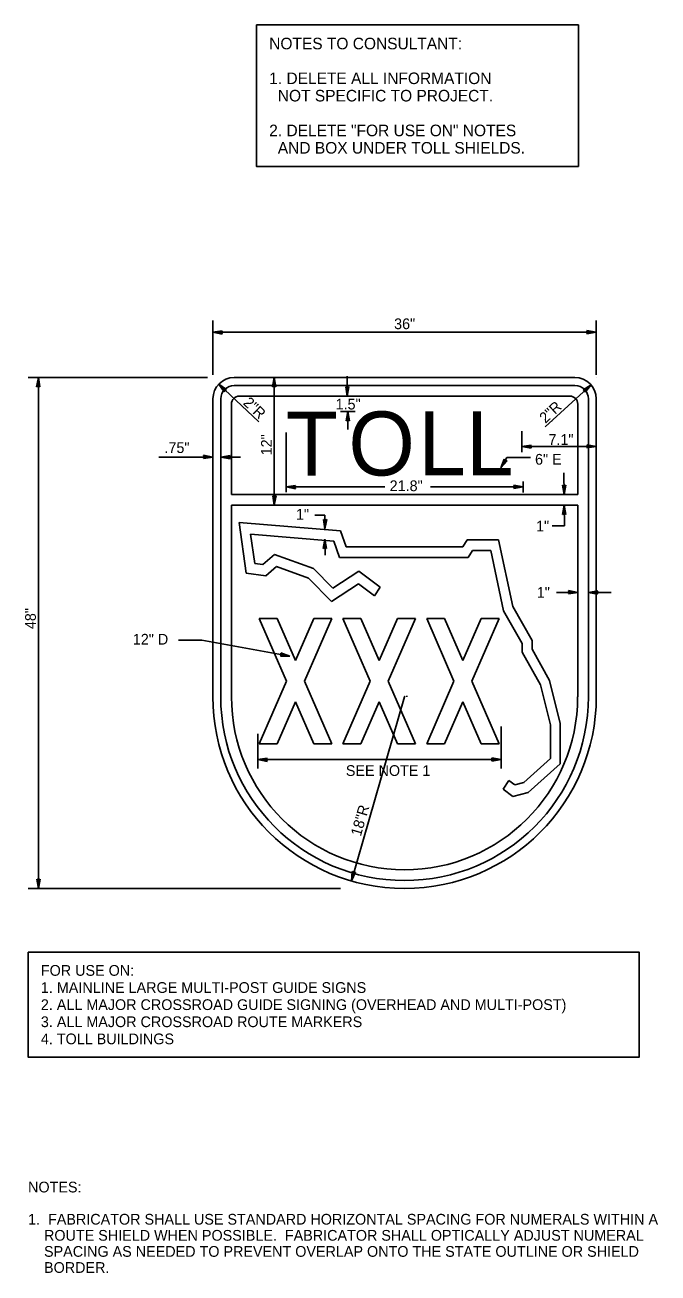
# Model space of a CAD drawing. Extents: x 52194 to 54069, y 8993 to 10153.
# Drawn here: x 52877 to 53372, y 9176 to 10153 of the extents above; entities that cross this region are included whole.
import ezdxf

# ---------------------------------------------------------------- set-up
doc = ezdxf.new("R2010")
doc.units = 0
for name, color, linetype in [('GSDims', 7, 'Continuous'), ('SignPanel', 7, 'Continuous'), ('TextAlert', 7, 'Continuous'), ('TextLabel', 7, 'Continuous'), ('TextNotes', 7, 'Continuous')]:
    doc.layers.add(name, color=color, linetype=linetype)

msp = doc.modelspace()

# ---------------------------------------------------------------- linework, layer by layer
at = {"layer": 'GSDims'}
for p, q in [((53023.82, 9879.03), (53023.82, 9921.63)), ((53323.82, 9879.03), (53323.82, 9921.63)), ((53023.82, 9912.43), (53031.12, 9913.53)), ((53023.82, 9912.43), (53030.82, 9912.93)), ((53023.82, 9912.43), (53031.12, 9911.03)), ((53023.82, 9912.43), (53030.82, 9911.63)), ((53323.82, 9912.43), (53023.82, 9912.43)), ((53030.62, 9912.33), (53031.12, 9913.53)), ((53031.12, 9911.03), (53030.62, 9912.33)), ((53323.82, 9912.43), (53316.52, 9913.83)), ((53316.52, 9913.83), (53317.02, 9912.53)), ((53317.02, 9912.53), (53316.52, 9911.23)), ((53323.82, 9912.43), (53316.52, 9911.23)), ((53323.82, 9912.43), (53316.82, 9913.13)), ((53323.82, 9912.43), (53316.82, 9911.93)), ((53019.42, 9877.03), (52879.12, 9877.03)), ((52887.22, 9877.03), (52885.82, 9869.73)), ((52885.82, 9869.73), (52887.12, 9870.23)), ((52887.22, 9877.03), (52886.42, 9870.03)), ((52887.12, 9870.23), (52888.32, 9869.73)), ((52887.22, 9877.03), (52888.32, 9869.73)), ((52887.22, 9877.03), (52887.72, 9870.03)), ((52887.22, 9877.03), (52887.22, 9477.03)), ((52923.72, 9877.03), (52923.72, 9877.03)), ((53028.42, 9871.88), (53059.72, 9842.43)), ((53028.42, 9871.88), (53034.52, 9867.68)), ((53028.42, 9871.88), (53032.72, 9865.88)), ((53028.42, 9871.88), (53033.02, 9866.58)), ((53028.42, 9871.88), (53033.92, 9867.38)), ((53071.82, 9877.03), (53070.42, 9869.73)), ((53070.42, 9869.73), (53071.72, 9870.33)), ((53071.82, 9877.03), (53071.12, 9870.03)), ((53071.72, 9870.33), (53073.02, 9869.73)), ((53071.82, 9877.03), (53073.02, 9869.73)), ((53071.82, 9877.03), (53072.32, 9870.03)), ((53071.82, 9777.03), (53071.82, 9877.03)), ((53128.87, 9862.43), (53127.72, 9869.73)), ((53128.97, 9869.18), (53127.72, 9869.73)), ((53128.87, 9862.43), (53128.37, 9869.43)), ((53128.87, 9862.43), (53128.87, 9878.08)), ((53128.87, 9862.43), (53130.27, 9869.68)), ((53128.87, 9862.43), (53129.62, 9869.43)), ((53130.27, 9869.68), (53128.97, 9869.18)), ((53319.77, 9871.28), (53283.92, 9838.33)), ((53319.77, 9871.28), (53313.47, 9867.38)), ((53319.77, 9871.28), (53314.07, 9867.08)), ((53319.77, 9871.28), (53314.97, 9866.18)), ((53319.77, 9871.28), (53315.17, 9865.48)), ((53323.82, 9877.03), (53323.82, 9877.03)), ((53032.72, 9865.88), (53033.22, 9867.18)), ((53033.22, 9867.18), (53034.52, 9867.68)), ((53313.47, 9867.38), (53314.67, 9866.78)), ((53314.67, 9866.78), (53315.17, 9865.48)), ((53123.72, 9850.38), (53135.12, 9850.38)), ((53129.42, 9850.38), (53128.02, 9843.13)), ((53129.42, 9850.38), (53128.67, 9843.38)), ((53129.42, 9850.38), (53129.42, 9836.43)), ((53129.42, 9850.38), (53130.57, 9843.08)), ((53129.42, 9850.38), (53129.92, 9843.38)), ((53128.02, 9843.13), (53129.32, 9843.63)), ((53129.32, 9843.63), (53130.57, 9843.08)), ((53289.47, 9842.43), (53289.47, 9842.43)), ((53081.12, 9787.23), (53081.12, 9834.03)), ((53265.62, 9818.48), (53265.62, 9835.03)), ((53265.62, 9823.03), (53272.92, 9824.18)), ((53265.62, 9823.03), (53272.62, 9823.53)), ((53265.62, 9823.03), (53323.82, 9823.03)), ((53265.62, 9823.03), (53272.87, 9821.63)), ((53265.62, 9823.03), (53272.62, 9822.28)), ((53272.37, 9822.93), (53272.92, 9824.18)), ((53272.87, 9821.63), (53272.37, 9822.93)), ((53317.07, 9823.13), (53316.52, 9821.88)), ((53323.82, 9823.03), (53316.52, 9821.88)), ((53323.82, 9823.03), (53316.57, 9824.43)), ((53316.57, 9824.43), (53317.07, 9823.13)), ((53323.82, 9823.03), (53316.82, 9823.78)), ((53323.82, 9823.03), (53316.82, 9822.53)), ((52981.47, 9814.73), (53023.82, 9814.73)), ((53023.82, 9814.73), (53016.52, 9816.13)), ((53016.52, 9816.13), (53017.02, 9814.83)), ((53017.02, 9814.83), (53016.52, 9813.63)), ((53023.82, 9814.73), (53016.52, 9813.63)), ((53023.82, 9814.73), (53016.82, 9815.53)), ((53023.82, 9814.73), (53016.82, 9814.23)), ((53030.02, 9814.73), (53037.32, 9815.93)), ((53030.02, 9814.73), (53037.02, 9815.23)), ((53030.02, 9814.73), (53037.22, 9813.33)), ((53030.02, 9814.73), (53037.02, 9814.03)), ((53030.02, 9814.73), (53045.32, 9814.73)), ((53036.72, 9814.63), (53037.32, 9815.93)), ((53037.22, 9813.33), (53036.72, 9814.63)), ((53249.07, 9806.28), (53253.77, 9814.43)), ((53249.07, 9806.28), (53251.67, 9813.18)), ((53249.07, 9806.28), (53252.17, 9812.58)), ((53249.07, 9806.28), (53253.17, 9811.98)), ((53249.07, 9806.28), (53253.97, 9811.88)), ((53252.57, 9812.08), (53251.67, 9813.18)), ((53253.97, 9811.88), (53252.57, 9812.08)), ((53272.42, 9814.43), (53253.77, 9814.43)), ((53298.62, 9785.38), (53298.42, 9802.28)), ((53081.12, 9791.33), (53088.42, 9792.53)), ((53081.12, 9791.33), (53088.12, 9791.83)), ((53081.12, 9791.33), (53088.42, 9789.93)), ((53081.12, 9791.33), (53088.12, 9790.63)), ((53081.12, 9791.33), (53158.22, 9791.33)), ((53087.82, 9791.23), (53088.42, 9792.53)), ((53088.42, 9789.93), (53087.82, 9791.23)), ((53193.98, 9791.33), (53266.52, 9791.33)), ((53266.52, 9791.33), (53259.22, 9792.73)), ((53259.22, 9792.73), (53259.82, 9791.43)), ((53259.82, 9791.43), (53259.22, 9790.13)), ((53266.52, 9791.33), (53259.22, 9790.13)), ((53266.52, 9791.33), (53259.52, 9792.03)), ((53266.52, 9791.33), (53259.52, 9790.83)), ((53266.52, 9786.98), (53266.52, 9795.48)), ((53298.62, 9785.38), (53297.32, 9792.68)), ((53298.62, 9792.08), (53297.32, 9792.68)), ((53298.62, 9785.38), (53298.02, 9792.38)), ((53298.62, 9785.38), (53299.92, 9792.68)), ((53299.92, 9792.68), (53298.62, 9792.08)), ((53298.62, 9785.38), (53299.22, 9792.38)), ((53071.82, 9777.03), (53070.62, 9784.33)), ((53071.92, 9783.73), (53070.62, 9784.33)), ((53071.82, 9777.03), (53071.32, 9784.03)), ((53071.82, 9777.03), (53073.22, 9784.33)), ((53071.82, 9777.03), (53072.52, 9784.03)), ((53073.22, 9784.33), (53071.92, 9783.73)), ((53298.72, 9777.13), (53297.32, 9769.83)), ((53298.72, 9777.13), (53298.02, 9770.13)), ((53298.72, 9777.13), (53298.92, 9760.98)), ((53298.72, 9777.13), (53299.92, 9769.83)), ((53298.72, 9777.13), (53299.22, 9770.13)), ((53111.45, 9769.28), (53103.55, 9769.28)), ((53111.45, 9758.58), (53110.25, 9765.88)), ((53111.55, 9765.28), (53110.25, 9765.88)), ((53111.45, 9758.58), (53110.95, 9765.58)), ((53111.45, 9758.58), (53111.45, 9769.28)), ((53111.45, 9758.58), (53112.85, 9765.88)), ((53111.45, 9758.58), (53112.15, 9765.58)), ((53112.85, 9765.88), (53111.55, 9765.28)), ((53297.32, 9769.83), (53298.62, 9770.33)), ((53298.62, 9770.33), (53299.92, 9769.83)), ((53298.92, 9760.98), (53289.22, 9760.98)), ((53111.45, 9750.38), (53110.15, 9743.08)), ((53110.15, 9743.08), (53111.45, 9743.68)), ((53111.45, 9750.38), (53110.85, 9743.38)), ((53111.45, 9750.38), (53111.65, 9737.88)), ((53111.45, 9750.38), (53112.75, 9743.08)), ((53111.45, 9750.38), (53112.05, 9743.38)), ((53111.45, 9743.68), (53112.75, 9743.08)), ((53309.32, 9708.83), (53292.82, 9708.83)), ((53309.32, 9708.83), (53302.02, 9710.23)), ((53302.02, 9710.23), (53302.52, 9708.93)), ((53302.52, 9708.93), (53302.02, 9707.73)), ((53309.32, 9708.83), (53302.02, 9707.73)), ((53309.32, 9708.83), (53302.32, 9709.63)), ((53309.32, 9708.83), (53302.32, 9708.33)), ((53317.62, 9708.83), (53324.92, 9710.03)), ((53317.62, 9708.83), (53324.62, 9709.33)), ((53317.62, 9708.83), (53324.82, 9707.43)), ((53317.62, 9708.83), (53324.62, 9708.13)), ((53335.52, 9708.83), (53317.62, 9708.83)), ((53324.32, 9708.73), (53324.92, 9710.03)), ((53324.82, 9707.43), (53324.32, 9708.73)), ((53015.14, 9671.37), (52996.74, 9671.37)), ((53015.14, 9671.37), (53083.95, 9658.74)), ((53077.35, 9660.07), (53076.55, 9658.92)), ((53083.95, 9658.74), (53076.55, 9658.92)), ((53083.95, 9658.74), (53076.97, 9659.52)), ((53083.95, 9658.74), (53077.06, 9661.44)), ((53077.06, 9661.44), (53077.35, 9660.07)), ((53083.95, 9658.74), (53077.21, 9660.72)), ((53173.82, 9627.03), (53132.22, 9482.93)), ((53173.79, 9627.02), (53173.79, 9627.02)), ((53173.79, 9627.02), (53173.79, 9627.02)), ((53058.92, 9597.97), (53058.92, 9570.97)), ((53249.36, 9603.76), (53249.36, 9570.97)), ((53058.92, 9577.87), (53066.22, 9579.07)), ((53058.92, 9577.87), (53065.92, 9578.37)), ((53058.92, 9577.87), (53066.22, 9576.47)), ((53058.92, 9577.87), (53065.92, 9577.17)), ((53058.92, 9577.87), (53138.57, 9577.87)), ((53065.62, 9577.77), (53066.22, 9579.07)), ((53066.22, 9576.47), (53065.62, 9577.77)), ((53138.57, 9577.87), (53249.36, 9577.87)), ((53249.36, 9577.87), (53242.06, 9579.27)), ((53242.06, 9579.27), (53242.66, 9577.97)), ((53242.66, 9577.97), (53242.06, 9576.67)), ((53249.36, 9577.87), (53242.06, 9576.67)), ((53249.36, 9577.87), (53242.36, 9578.57)), ((53249.36, 9577.87), (53242.36, 9577.37)), ((53132.22, 9482.93), (53132.87, 9490.28)), ((53132.22, 9482.93), (53133.47, 9489.88)), ((53132.22, 9482.93), (53135.37, 9489.63)), ((53132.22, 9482.93), (53134.67, 9489.53)), ((53132.87, 9490.28), (53134.02, 9489.43)), ((53134.02, 9489.43), (53135.37, 9489.63)), ((52887.22, 9477.03), (52886.02, 9484.33)), ((52887.32, 9483.73), (52886.02, 9484.33)), ((52887.22, 9477.03), (52886.72, 9484.03)), ((52887.22, 9477.03), (52888.62, 9484.33)), ((52887.22, 9477.03), (52887.92, 9484.03)), ((52888.62, 9484.33), (52887.32, 9483.73)), ((53123.62, 9477.03), (52879.12, 9477.03))]:
    msp.add_line(p, q, dxfattribs=at)
for radius in [0.141, 0.141, 0.0707]:
    msp.add_circle((53173.79, 9627.07), radius, dxfattribs=at)
at = {"layer": 'SignPanel'}
for p, q in [((53040.47, 9877.03), (53307.17, 9877.03)), ((53040.47, 9870.73), (53307.17, 9870.73)), ((53023.72, 9627.13), (53023.82, 9860.38)), ((53029.92, 9627.13), (53030.02, 9860.38)), ((53044.52, 9862.43), (53303.12, 9862.43)), ((53317.62, 9627.03), (53317.62, 9860.38)), ((53323.82, 9627.03), (53323.82, 9860.38)), ((53038.32, 9785.33), (53038.32, 9856.23)), ((53309.32, 9785.33), (53309.32, 9856.23)), ((53038.32, 9785.33), (53309.32, 9785.33)), ((53038.32, 9627.03), (53038.32, 9777.03)), ((53038.32, 9777.03), (53309.32, 9777.03)), ((53309.32, 9627.03), (53309.32, 9777.03)), ((53044.24, 9763.62), (53123.74, 9756.91)), ((53049.9, 9723.86), (53044.24, 9763.62)), ((53118.34, 9748.96), (53053.31, 9754.45)), ((53053.31, 9754.45), (53056.59, 9731.41)), ((53123.74, 9756.91), (53128.19, 9744.41)), ((53122.94, 9736.03), (53118.34, 9748.96)), ((53128.19, 9744.41), (53219.37, 9744.41)), ((53219.37, 9744.41), (53222.81, 9749.97)), ((53222.81, 9749.97), (53247.34, 9749.97)), ((53247.34, 9749.97), (53258.45, 9697.71)), ((53062.89, 9730.55), (53071.92, 9738.33)), ((53071.92, 9738.33), (53102.59, 9727.42)), ((53223.44, 9736.03), (53122.94, 9736.03)), ((53226.88, 9741.59), (53223.44, 9736.03)), ((53241.25, 9741.59), (53226.88, 9741.59)), ((53251.27, 9694.46), (53241.25, 9741.59)), ((53065.12, 9721.81), (53049.9, 9723.86)), ((53056.59, 9731.41), (53062.89, 9730.55)), ((53073.45, 9728.97), (53065.12, 9721.81)), ((53098.62, 9720.02), (53073.45, 9728.97)), ((53102.59, 9727.42), (53117.64, 9712.17)), ((53117.64, 9712.17), (53138.05, 9725.28)), ((53138.05, 9725.28), (53154.66, 9713)), ((53116.61, 9701.78), (53098.62, 9720.02)), ((53137.77, 9715.37), (53116.61, 9701.78)), ((53150.37, 9706.06), (53137.77, 9715.37)), ((53154.66, 9713), (53150.37, 9706.06)), ((53265.9, 9668.76), (53251.27, 9694.46)), ((53258.45, 9697.71), (53273.57, 9671.15)), ((53074.11, 9688.47), (53060.1, 9688.47)), ((53060.1, 9688.47), (53081.46, 9639.3)), ((53088.47, 9655.42), (53074.11, 9688.47)), ((53102.83, 9688.47), (53088.47, 9655.42)), ((53095.47, 9639.3), (53116.84, 9688.47)), ((53116.84, 9688.47), (53102.83, 9688.47)), ((53139.6, 9688.47), (53125.59, 9688.47)), ((53125.59, 9688.47), (53146.95, 9639.3)), ((53153.96, 9655.42), (53139.6, 9688.47)), ((53168.32, 9688.47), (53153.96, 9655.42)), ((53160.96, 9639.3), (53182.33, 9688.47)), ((53182.33, 9688.47), (53168.32, 9688.47)), ((53205.09, 9688.47), (53191.08, 9688.47)), ((53191.08, 9688.47), (53212.44, 9639.3)), ((53219.45, 9655.42), (53205.09, 9688.47)), ((53233.81, 9688.47), (53219.45, 9655.42)), ((53226.45, 9639.3), (53247.82, 9688.47)), ((53247.82, 9688.47), (53233.81, 9688.47)), ((53265.9, 9662.1), (53265.9, 9668.76)), ((53273.57, 9671.15), (53273.57, 9664.45)), ((53273.57, 9664.45), (53287.25, 9639.82)), ((53280.13, 9636.47), (53265.9, 9662.1)), ((53081.46, 9639.3), (53060.1, 9590.13)), ((53116.84, 9590.13), (53095.47, 9639.3)), ((53146.95, 9639.3), (53125.59, 9590.13)), ((53182.33, 9590.13), (53160.96, 9639.3)), ((53212.44, 9639.3), (53191.08, 9590.13)), ((53247.82, 9590.13), (53226.45, 9639.3)), ((53288, 9605.01), (53280.13, 9636.47)), ((53287.25, 9639.82), (53295.67, 9606.13)), ((53074.11, 9590.13), (53088.47, 9623.18)), ((53088.47, 9623.18), (53102.83, 9590.13)), ((53139.6, 9590.13), (53153.96, 9623.18)), ((53153.96, 9623.18), (53168.32, 9590.13)), ((53205.09, 9590.13), (53219.45, 9623.18)), ((53219.45, 9623.18), (53233.81, 9590.13)), ((53295.67, 9606.13), (53295.67, 9574.65)), ((53288, 9578.62), (53288, 9605.01)), ((53060.1, 9590.13), (53074.11, 9590.13)), ((53102.83, 9590.13), (53116.84, 9590.13)), ((53125.59, 9590.13), (53139.6, 9590.13)), ((53168.32, 9590.13), (53182.33, 9590.13)), ((53191.08, 9590.13), (53205.09, 9590.13)), ((53233.81, 9590.13), (53247.82, 9590.13)), ((53267.06, 9559.85), (53288, 9578.62)), ((53295.67, 9574.65), (53270.56, 9552.15)), ((53251.07, 9554.76), (53255.44, 9561.65)), ((53255.44, 9561.65), (53260.18, 9558.05)), ((53260.18, 9558.05), (53267.06, 9559.85)), ((53258.63, 9549.03), (53251.07, 9554.76)), ((53270.56, 9552.15), (53258.63, 9549.03))]:
    msp.add_line(p, q, dxfattribs=at)
for centre, radius, start, end in [((53040.48, 9860.37), 16.67, 90, 179.97628), ((53040.48, 9860.37), 10.47, 90, 179.97628), ((53307.15, 9860.37), 16.67, 0, 90), ((53307.15, 9860.37), 10.47, 0, 90), ((53044.52, 9856.23), 6.2, 90, 180), ((53303.12, 9856.23), 6.2, 0, 90), ((53173.77, 9627.08), 150.05, 179.98091, 359.98091), ((53173.77, 9627.08), 143.85, 179.98091, 359.98091), ((53173.77, 9627.08), 135.45, 179.98091, 359.98091)]:
    msp.add_arc(centre, radius, start, end, dxfattribs=at)
at = {"layer": 'TextAlert'}
msp.add_lwpolyline([(53057.85, 10153.03), (53309.86, 10153.03), (53309.86, 10042.31), (53057.85, 10042.31)], close=True, dxfattribs=at)
at = {"layer": 'TextLabel'}
msp.add_lwpolyline([(52879.12, 9427.03), (53357.47, 9427.03), (53357.47, 9345.03), (52879.12, 9345.03)], close=True, dxfattribs=at)

# ---------------------------------------------------------------- texts
at = {"layer": 'GSDims'}
for s, p in [('36"', (53165.6, 9914.86)), ('1.5"', (53119.8, 9851.98)), ('7.1"', (53286.39, 9824.28)), ('.75"', (52985.86, 9817.91)), ('6" E', (53275.91, 9808.78)), ('21.8"', (53162.11, 9788.05)), ('1"', (53088.78, 9765.72)), ('1"', (53276.71, 9756.48)), ('1"', (53277.27, 9704.6)), ('12" D', (52961.1, 9667.92)), ('SEE NOTE 1', (53127.82, 9565.11))]:
    msp.add_text(s, height=8.4, dxfattribs=at).set_placement(p)
for s, rotation, p in [('2"R', 316.51741, (53046.91, 9856.53)), ('2"R', 42.57524, (53284.01, 9840.73)), ('12"', 90, (53069.86, 9816.08)), ('48"', 90, (52885.21, 9680.03)), ('.', 90, (53176.29, 9625.92)), ('18"R', 73.85566, (53139.51, 9517.33))]:
    msp.add_text(s, height=8.4, rotation=rotation, dxfattribs=at).set_placement(p)
at = {"layer": 'SignPanel'}
for s, height, p in [('T', 50.08, (53080.71, 9800.18)), ('O', 50.08, (53129.81, 9800.33)), ('LL', 50.082, (53184.56, 9800.53))]:
    msp.add_text(s, height=height, dxfattribs=at).set_placement(p)
at = {"layer": 'TextAlert'}
for s, p in [('NOTES TO CONSULTANT:', (53067.85, 10133.96)), ('1. DELETE ALL INFORMATION', (53067.85, 10106.74)), ('  NOT SPECIFIC TO PROJECT.', (53067.85, 10093.14)), ('2. DELETE "FOR USE ON" NOTES', (53067.85, 10065.92)), ('  AND BOX UNDER TOLL SHIELDS.', (53067.85, 10052.31))]:
    msp.add_text(s, height=9.072, dxfattribs=at).set_placement(p)
at = {"layer": 'TextLabel'}
for s, p in [('FOR USE ON:', (52889.12, 9408.63)), ('1. MAINLINE LARGE MULTI-POST GUIDE SIGNS', (52889.12, 9395.23)), ('2. ALL MAJOR CROSSROAD GUIDE SIGNING (OVERHEAD AND MULTI-POST)', (52889.12, 9381.83)), ('3. ALL MAJOR CROSSROAD ROUTE MARKERS', (52889.12, 9368.43)), ('4. TOLL BUILDINGS', (52889.12, 9355.03))]:
    msp.add_text(s, height=8.4, dxfattribs=at).set_placement(p)
at = {"layer": 'TextNotes'}
for s, p in [('NOTES:', (52879.12, 9239.03)), ('1.  FABRICATOR SHALL USE STANDARD HORIZONTAL SPACING FOR NUMERALS WITHIN A', (52879.12, 9213.83)), ('    ROUTE SHIELD WHEN POSSIBLE.  FABRICATOR SHALL OPTICALLY ADJUST NUMERAL', (52879.12, 9201.23)), ('    SPACING AS NEEDED TO PREVENT OVERLAP ONTO THE STATE OUTLINE OR SHIELD ', (52879.12, 9188.63)), ('    BORDER.', (52879.12, 9176.03))]:
    msp.add_text(s, height=8.4, dxfattribs=at).set_placement(p)

doc.saveas('drawing.dxf')
